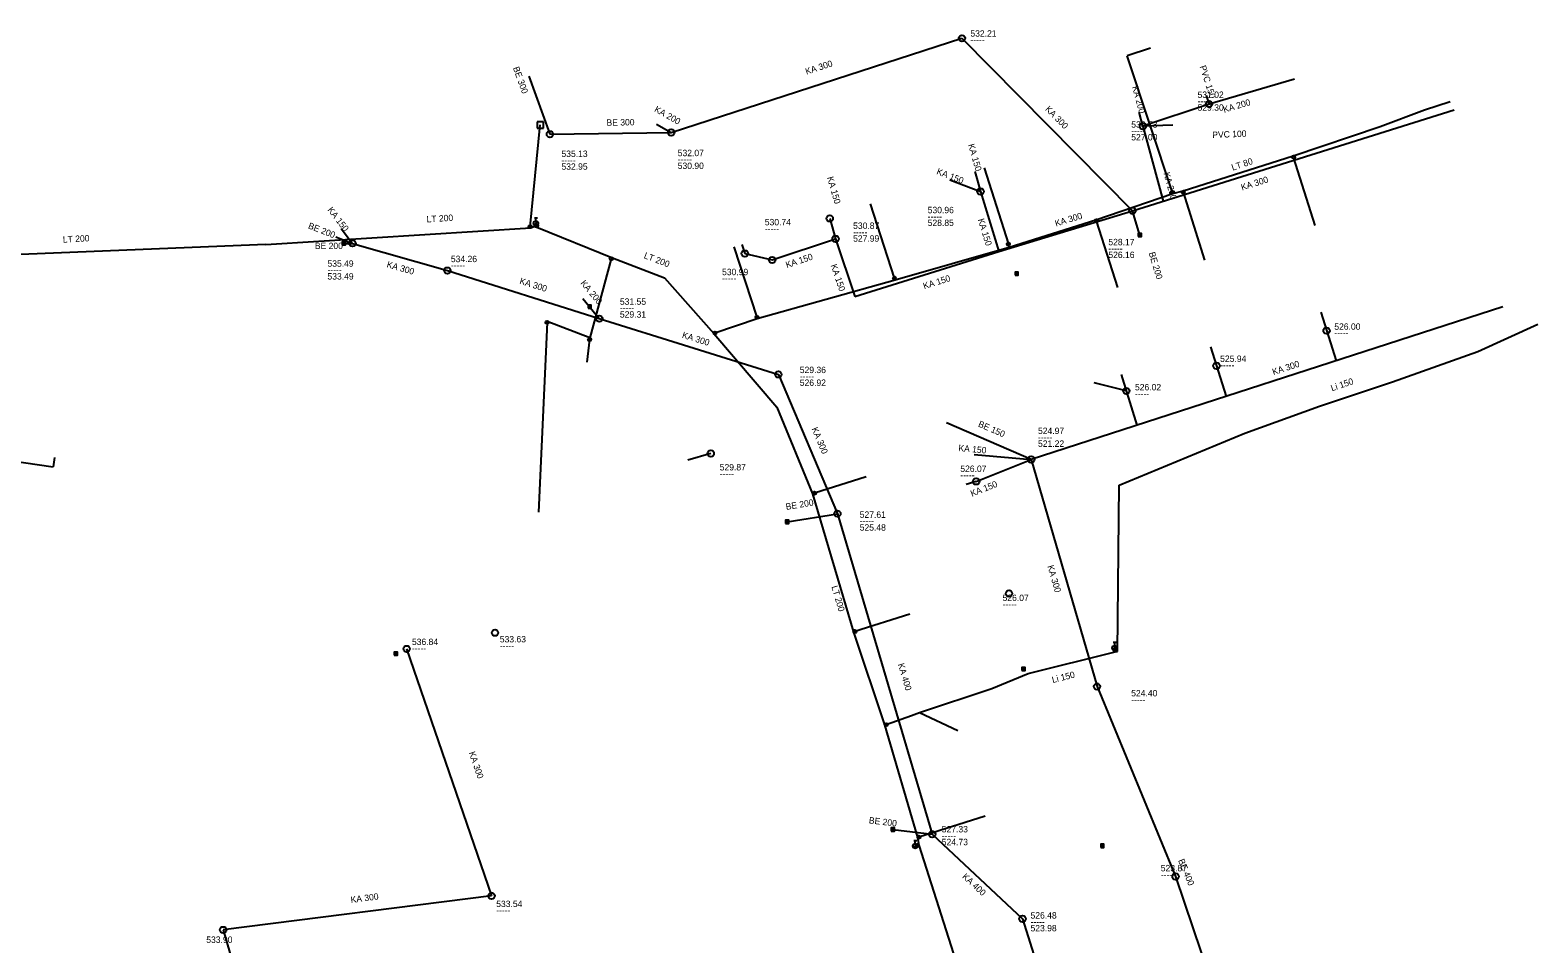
# Model space of a CAD drawing. Extents: x -769542 to -769122, y -1181691 to -1181360.
# Drawn here: x -769357.9 to -769122.2, y -1181503.2 to -1181360.4 of the extents above; entities that cross this region are included whole.
import ezdxf

# ---------------------------------------------------------------- set-up
doc = ezdxf.new("R2010")
doc.units = 0
for name, color, linetype in [('Level 19', 7, 'Continuous'), ('Level 20', 7, 'Continuous'), ('Level 21', 7, 'Continuous'), ('Level 24', 7, 'Continuous'), ('Level 26', 7, 'Continuous'), ('Level 29', 7, 'Continuous'), ('Level 40', 7, 'Continuous'), ('Level 41', 7, 'Continuous'), ('Level 44', 7, 'Continuous'), ('Level 45', 7, 'Continuous'), ('Level 46', 7, 'Continuous')]:
    doc.layers.add(name, color=color, linetype=linetype)

msp = doc.modelspace()

# ---------------------------------------------------------------- linework, layer by layer
at = {"layer": 'Level 19'}
for p, q in [((-769182.75, -1181363.17), (-769186.37, -1181364.36)), ((-769179.31, -1181385.73), (-769186.37, -1181364.36)), ((-769279.75, -1181391.1), (-769278.16, -1181375.19)), ((-769160.36, -1181380.2), (-769160.45, -1181380.04)), ((-769157, -1181390.91), (-769160.36, -1181380.2)), ((-769208.75, -1181381.9), (-769204.97, -1181393.84)), ((-769179.25, -1181385.92), (-769179.31, -1181385.73)), ((-769177.63, -1181385.47), (-769177.59, -1181385.7)), ((-769174.25, -1181396.33), (-769177.59, -1181385.7)), ((-769222.77, -1181399.16), (-769226.53, -1181387.52)), ((-769279.65, -1181391.3), (-769279.75, -1181391.1)), ((-769191.31, -1181390), (-769191.19, -1181390.17)), ((-769187.86, -1181400.63), (-769191.19, -1181390.17)), ((-769244.26, -1181405.26), (-769247.84, -1181394.26)), ((-769204.85, -1181394.31), (-769204.97, -1181393.84)), ((-769267.07, -1181396.11), (-769270.41, -1181408.5)), ((-769266.89, -1181395.96), (-769267.07, -1181396.11)), ((-769222.66, -1181399.42), (-769222.77, -1181399.16)), ((-769244.22, -1181405.43), (-769244.26, -1181405.26)), ((-769277.1, -1181406.06), (-769278.46, -1181435.74)), ((-769277.07, -1181405.94), (-769277.1, -1181406.06)), ((-769270.41, -1181408.5), (-769277.07, -1181405.94)), ((-769270.45, -1181408.75), (-769270.9, -1181412.3)), ((-769270.41, -1181408.5), (-769270.45, -1181408.75)), ((-769376.52, -1181425.51), (-769354.33, -1181428.62)), ((-769354.1, -1181427.21), (-769354.33, -1181428.62)), ((-769227.19, -1181430.21), (-769235.27, -1181432.76)), ((-769235.57, -1181432.87), (-769235.27, -1181432.76)), ((-769220.36, -1181451.66), (-769228.96, -1181454.4)), ((-769229.16, -1181454.48), (-769228.96, -1181454.4)), ((-769218.88, -1181467.07), (-769212.85, -1181469.89)), ((-769208.6, -1181483.28), (-769218.95, -1181486.55)), ((-769219.19, -1181486.6), (-769218.95, -1181486.55))]:
    msp.add_line(p, q, dxfattribs=at)
at = {"layer": 'Level 20'}
for p, q in [((-769139.91, -1181372.81), (-769135.9, -1181371.5)), ((-769146.83, -1181375.45), (-769139.91, -1181372.81)), ((-769160.45, -1181380.04), (-769146.83, -1181375.45)), ((-769177.63, -1181385.47), (-769160.45, -1181380.04)), ((-769191.31, -1181390), (-769179.25, -1181385.92)), ((-769179.25, -1181385.92), (-769177.63, -1181385.47)), ((-769279.65, -1181391.3), (-769278.99, -1181391.03)), ((-769278.99, -1181391.03), (-769278.71, -1181391.19)), ((-769278.73, -1181390.98), (-769278.84, -1181390.57)), ((-769278.71, -1181391.19), (-769278.73, -1181390.98)), ((-769204.85, -1181394.31), (-769191.31, -1181390)), ((-769321.1, -1181393.86), (-769279.65, -1181391.3)), ((-769278.71, -1181391.19), (-769266.89, -1181395.96)), ((-769321.1, -1181393.86), (-769371.45, -1181395.91)), ((-769222.66, -1181399.42), (-769204.85, -1181394.31)), ((-769266.89, -1181395.96), (-769258.74, -1181399.09)), ((-769258.74, -1181399.09), (-769251.02, -1181407.79)), ((-769244.22, -1181405.43), (-769222.66, -1181399.42)), ((-769250.85, -1181407.71), (-769244.22, -1181405.43)), ((-769131.58, -1181410.62), (-769122.17, -1181406.35)), ((-769251.02, -1181407.79), (-769250.85, -1181407.71)), ((-769251.02, -1181407.79), (-769241.16, -1181419.29)), ((-769144.92, -1181415.35), (-769131.58, -1181410.62)), ((-769156.29, -1181419.18), (-769144.92, -1181415.35)), ((-769241.16, -1181419.29), (-769235.57, -1181432.87)), ((-769168.01, -1181423.4), (-769156.29, -1181419.18)), ((-769187.65, -1181431.52), (-769168.01, -1181423.4)), ((-769235.57, -1181432.87), (-769229.16, -1181454.48)), ((-769187.88, -1181457.52), (-769187.65, -1181431.52)), ((-769229.16, -1181454.48), (-769224.35, -1181469)), ((-769188.33, -1181457.22), (-769188.34, -1181456.96)), ((-769201.88, -1181460.98), (-769188.27, -1181457.55)), ((-769188.27, -1181457.55), (-769188.33, -1181457.22)), ((-769188.27, -1181457.55), (-769187.88, -1181457.52)), ((-769207.54, -1181463.28), (-769201.88, -1181460.98)), ((-769218.88, -1181467.07), (-769207.54, -1181463.28)), ((-769224.35, -1181469), (-769224.06, -1181468.96)), ((-769224.06, -1181468.96), (-769220.09, -1181467.52)), ((-769220.09, -1181467.52), (-769218.88, -1181467.07)), ((-769224.35, -1181469), (-769219.19, -1181486.6)), ((-769219.19, -1181486.6), (-769218.94, -1181487.79)), ((-769218.94, -1181487.79), (-769219.19, -1181487.87)), ((-769218.94, -1181487.79), (-769212.39, -1181508.39)), ((-769219.19, -1181487.87), (-769219.52, -1181487.95))]:
    msp.add_line(p, q, dxfattribs=at)
at = {"layer": 'Level 21'}
for p, q in [((-769279.134, -1181390.801), (-769278.544, -1181390.338)), ((-769279.09, -1181389.695), (-769278.59, -1181389.695)), ((-769278.84, -1181390.195), (-769278.84, -1181389.695)), ((-769188.634, -1181457.191), (-769188.044, -1181456.728)), ((-769188.59, -1181456.085), (-769188.09, -1181456.085)), ((-769188.34, -1181456.585), (-769188.34, -1181456.085)), ((-769219.814, -1181488.181), (-769219.224, -1181487.718)), ((-769219.77, -1181487.075), (-769219.27, -1181487.075)), ((-769219.52, -1181487.575), (-769219.52, -1181487.075))]:
    msp.add_line(p, q, dxfattribs=at)
for centre in [(-769278.84, -1181390.57), (-769188.34, -1181456.96), (-769219.52, -1181487.95)]:
    msp.add_circle(centre, 0.375, dxfattribs=at)
at = {"layer": 'Level 26'}
for centre in [(-769160.36, -1181380.2), (-769179.31, -1181385.73), (-769177.59, -1181385.7), (-769279.75, -1181391.1), (-769278.73, -1181390.98), (-769191.19, -1181390.17), (-769267.07, -1181396.11), (-769204.97, -1181393.84), (-769222.77, -1181399.16), (-769244.26, -1181405.26), (-769277.1, -1181406.06), (-769250.85, -1181407.71), (-769270.45, -1181408.75), (-769235.27, -1181432.76), (-769228.96, -1181454.4), (-769188.33, -1181457.22), (-769224.06, -1181468.96), (-769219.19, -1181487.87), (-769218.95, -1181486.55)]:
    msp.add_circle(centre, 0.25, dxfattribs=at)
at = {"layer": 'Level 29'}
for p, q in [((-769277.66, -1181374.69), (-769278.66, -1181374.69)), ((-769278.66, -1181374.69), (-769278.66, -1181375.69)), ((-769278.66, -1181375.69), (-769277.66, -1181375.69)), ((-769277.66, -1181375.69), (-769277.66, -1181374.69))]:
    msp.add_line(p, q, dxfattribs=at)
at = {"layer": 'Level 40'}
for p, q in [((-769257.69, -1181376.37), (-769212.22, -1181361.64)), ((-769212.22, -1181361.64), (-769185.56, -1181388.6)), ((-769279.93, -1181367.57), (-769276.65, -1181376.64)), ((-769160.22, -1181368.02), (-769173.59, -1181371.92)), ((-769173.59, -1181371.92), (-769183.93, -1181375.38)), ((-769185.56, -1181388.6), (-769135.28, -1181372.8)), ((-769276.65, -1181376.64), (-769257.69, -1181376.37)), ((-769183.93, -1181375.38), (-769180.75, -1181387.09)), ((-769209.32, -1181385.6), (-769206.44, -1181395)), ((-769206.44, -1181395), (-769185.56, -1181388.6)), ((-769232.9, -1181389.81), (-769231.99, -1181393)), ((-769241.9, -1181396.3), (-769231.99, -1181393)), ((-769231.99, -1181393), (-769228.95, -1181402.03)), ((-769307.52, -1181393.7), (-769292.69, -1181397.96)), ((-769246.17, -1181395.3), (-769241.9, -1181396.3)), ((-769228.95, -1181402.03), (-769206.44, -1181395)), ((-769292.69, -1181397.96), (-769268.94, -1181405.47)), ((-769127.67, -1181403.61), (-769201.4, -1181427.5)), ((-769268.94, -1181405.47), (-769240.93, -1181414.2)), ((-769240.93, -1181414.2), (-769231.7, -1181435.97)), ((-769210, -1181430.93), (-769201.4, -1181427.5)), ((-769201.4, -1181427.5), (-769191.1, -1181463.01)), ((-769231.7, -1181435.97), (-769216.88, -1181486.1)), ((-769299.06, -1181457.11), (-769285.78, -1181495.74)), ((-769191.1, -1181463.01), (-769178.82, -1181492.7)), ((-769216.88, -1181486.1), (-769202.76, -1181499.32)), ((-769178.82, -1181492.7), (-769159.28, -1181550.75)), ((-769285.78, -1181495.74), (-769327.75, -1181501.05)), ((-769202.76, -1181499.32), (-769190.37, -1181538.88)), ((-769327.75, -1181501.05), (-769324.09, -1181513.66))]:
    msp.add_line(p, q, dxfattribs=at)
at = {"layer": 'Level 41'}
for centre in [(-769212.22, -1181361.64), (-769173.59, -1181371.92), (-769276.65, -1181376.64), (-769257.69, -1181376.37), (-769183.93, -1181375.38), (-769209.32, -1181385.6), (-769185.56, -1181388.6), (-769232.9, -1181389.81), (-769307.52, -1181393.7), (-769231.99, -1181393), (-769246.17, -1181395.3), (-769241.9, -1181396.3), (-769292.69, -1181397.96), (-769268.94, -1181405.47), (-769155.21, -1181407.36), (-769172.42, -1181412.85), (-769240.93, -1181414.2), (-769240.93, -1181414.2), (-769186.52, -1181416.78), (-769251.5, -1181426.56), (-769201.4, -1181427.5), (-769210, -1181430.93), (-769231.7, -1181435.97), (-769204.86, -1181448.45), (-769285.24, -1181454.59), (-769299.06, -1181457.11), (-769191.1, -1181463.01), (-769216.88, -1181486.1), (-769178.82, -1181492.7), (-769285.78, -1181495.74), (-769202.76, -1181499.32), (-769327.75, -1181501.05)]:
    msp.add_circle(centre, 0.5, dxfattribs=at)
at = {"layer": 'Level 45'}
for p, q in [((-769174.02, -1181370.57), (-769173.59, -1181371.92)), ((-769183.93, -1181375.38), (-769184.52, -1181373.2)), ((-769259.99, -1181375.07), (-769257.69, -1181376.37)), ((-769179.26, -1181375.2), (-769183.93, -1181375.38)), ((-769214.1, -1181383.77), (-769209.32, -1181385.6)), ((-769210.22, -1181382.48), (-769209.32, -1181385.6)), ((-769184.42, -1181392.4), (-769185.56, -1181388.6)), ((-769310.11, -1181392.69), (-769307.52, -1181393.7)), ((-769309.32, -1181391.38), (-769307.52, -1181393.7)), ((-769308.89, -1181393.7), (-769307.52, -1181393.7)), ((-769246.62, -1181393.87), (-769246.17, -1181395.3)), ((-769271.52, -1181402.34), (-769268.94, -1181405.47)), ((-769156.12, -1181404.47), (-769153.73, -1181412.06)), ((-769173.35, -1181409.87), (-769170.93, -1181417.63)), ((-769187.32, -1181414.2), (-769184.86, -1181422.14)), ((-769186.52, -1181416.78), (-769191.55, -1181415.51)), ((-769201.4, -1181427.5), (-769214.62, -1181421.75)), ((-769251.5, -1181426.56), (-769255.09, -1181427.6)), ((-769210.32, -1181426.71), (-769201.4, -1181427.5)), ((-769210, -1181430.93), (-769211.59, -1181431.41)), ((-769239.55, -1181437.26), (-769231.7, -1181435.97)), ((-769223.02, -1181485.36), (-769216.88, -1181486.1))]:
    msp.add_line(p, q, dxfattribs=at)
at = {"layer": 'Level 46'}
for p, q in [((-769184.67, -1181392.4), (-769184.17, -1181392.4)), ((-769309.14, -1181393.7), (-769308.64, -1181393.7)), ((-769203.92, -1181398.44), (-769203.42, -1181398.44)), ((-769270.68, -1181403.61), (-769270.18, -1181403.61)), ((-769239.8, -1181437.26), (-769239.3, -1181437.26)), ((-769301.01, -1181457.86), (-769300.51, -1181457.86)), ((-769202.86, -1181460.26), (-769202.36, -1181460.26)), ((-769223.27, -1181485.36), (-769222.77, -1181485.36)), ((-769190.52, -1181487.91), (-769190.02, -1181487.91))]:
    msp.add_line(p, q, dxfattribs=at)
for points in [[(-769309.14, -1181393.951), (-769308.6395, -1181393.951), (-769308.6395, -1181393.4495), (-769309.14, -1181393.4495)], [(-769184.67, -1181392.651), (-769184.1695, -1181392.651), (-769184.1695, -1181392.1495), (-769184.67, -1181392.1495)], [(-769203.92, -1181398.691), (-769203.4195, -1181398.691), (-769203.4195, -1181398.1895), (-769203.92, -1181398.1895)], [(-769270.68, -1181403.861), (-769270.1795, -1181403.861), (-769270.1795, -1181403.3595), (-769270.68, -1181403.3595)], [(-769239.8, -1181437.511), (-769239.2995, -1181437.511), (-769239.2995, -1181437.0095), (-769239.8, -1181437.0095)], [(-769301.01, -1181458.111), (-769300.5095, -1181458.111), (-769300.5095, -1181457.6095), (-769301.01, -1181457.6095)], [(-769202.86, -1181460.511), (-769202.3595, -1181460.511), (-769202.3595, -1181460.0095), (-769202.86, -1181460.0095)], [(-769223.27, -1181485.611), (-769222.7695, -1181485.611), (-769222.7695, -1181485.1095), (-769223.27, -1181485.1095)], [(-769190.52, -1181488.161), (-769190.0195, -1181488.161), (-769190.0195, -1181487.6595), (-769190.52, -1181487.6595)]]:
    msp.add_lwpolyline(points, close=True, dxfattribs=at)

# ---------------------------------------------------------------- texts
at = {"layer": 'Level 24'}
for s, rotation, p in [('LT 80', 18.624, (-769169.88, -1181382.35)), ('LT 200', 3.534, (-769295.91, -1181390.43)), ('LT 200', 3.1, (-769352.79, -1181393.6)), ('LT 200', 338.991, (-769262.05, -1181395.99)), ('Li 150', 18.616, (-769154.36, -1181416.84)), ('LT 200', 286.522, (-769232.65, -1181447.38)), ('Li 150', 14.145, (-769198.02, -1181462.46))]:
    msp.add_text(s, height=1, rotation=rotation, dxfattribs=at).set_placement(p)
at = {"layer": 'Level 44'}
for s, p in [('532.21', (-769210.9, -1181361.38)), ('-----', (-769210.9, -1181362.38)), ('531.02', (-769175.38, -1181370.96)), ('529.30', (-769175.38, -1181372.96)), ('-----', (-769175.38, -1181371.96)), ('530.73', (-769185.75, -1181375.61)), ('527.00', (-769185.75, -1181377.61)), ('-----', (-769185.75, -1181376.61)), ('535.13', (-769274.85, -1181380.19)), ('532.07', (-769256.67, -1181380.07)), ('532.95', (-769274.85, -1181382.19)), ('-----', (-769274.85, -1181381.19)), ('530.90', (-769256.67, -1181382.07)), ('-----', (-769256.67, -1181381.07)), ('530.96', (-769217.58, -1181388.99)), ('530.74', (-769243.05, -1181390.88)), ('530.87', (-769229.24, -1181391.44)), ('528.85', (-769217.58, -1181390.99)), ('-----', (-769217.58, -1181389.99)), ('-----', (-769243.05, -1181391.88)), ('527.99', (-769229.24, -1181393.44)), ('-----', (-769229.24, -1181392.44)), ('528.17', (-769189.33, -1181394)), ('BE 200', (-769313.41, -1181394.59)), ('534.26', (-769292.14, -1181396.64)), ('526.16', (-769189.33, -1181396)), ('-----', (-769189.33, -1181395)), ('535.49', (-769311.44, -1181397.36)), ('-----', (-769311.44, -1181398.36)), ('-----', (-769292.14, -1181397.64)), ('530.99', (-769249.73, -1181398.68)), ('533.49', (-769311.44, -1181399.36)), ('-----', (-769249.73, -1181399.68)), ('531.55', (-769265.71, -1181403.31)), ('529.31', (-769265.71, -1181405.31)), ('-----', (-769265.71, -1181404.31)), ('526.00', (-769154, -1181407.22)), ('-----', (-769154, -1181408.22)), ('525.94', (-769171.85, -1181412.24)), ('529.36', (-769237.58, -1181413.99)), ('-----', (-769237.58, -1181414.99)), ('-----', (-769171.85, -1181413.24)), ('526.92', (-769237.58, -1181415.99)), ('526.02', (-769185.17, -1181416.69)), ('-----', (-769185.17, -1181417.69)), ('524.97', (-769200.33, -1181423.52)), ('-----', (-769200.33, -1181424.52)), ('521.22', (-769200.33, -1181425.52)), ('529.87', (-769250.1, -1181429.21)), ('526.07', (-769212.48, -1181429.44)), ('-----', (-769250.1, -1181430.21)), ('-----', (-769212.48, -1181430.44)), ('527.61', (-769228.21, -1181436.62)), ('525.48', (-769228.21, -1181438.62)), ('-----', (-769228.21, -1181437.62)), ('526.07', (-769205.87, -1181449.62)), ('-----', (-769205.87, -1181450.62)), ('536.84', (-769298.23, -1181456.51)), ('-----', (-769298.23, -1181457.51)), ('533.63', (-769284.49, -1181456.1)), ('-----', (-769284.49, -1181457.1)), ('524.40', (-769185.76, -1181464.54)), ('-----', (-769185.76, -1181465.54)), ('527.33', (-769215.38, -1181485.81)), ('524.73', (-769215.38, -1181487.81)), ('-----', (-769215.38, -1181486.81)), ('523.87', (-769181.13, -1181491.89)), ('-----', (-769181.13, -1181492.89)), ('533.54', (-769285.05, -1181497.48)), ('-----', (-769285.05, -1181498.48)), ('526.48', (-769201.5, -1181499.28)), ('523.98', (-769201.5, -1181501.28)), ('-----', (-769201.5, -1181500.28)), ('533.90', (-769330.39, -1181503.08))]:
    msp.add_text(s, height=1, dxfattribs=at).set_placement(p)
for s, rotation, p in [('KA 300', 17.95, (-769236.53, -1181367.33)), ('BE 300', 289.89, (-769282.45, -1181366.27)), ('PVC 150', 287.668, (-769175.07, -1181366.05)), ('KA 200', 285.144, (-769185.63, -1181369.24)), ('KA 200', 330.583, (-769260.42, -1181373.03)), ('KA 300', 314.679, (-769199.29, -1181372.8)), ('KA 200', 16.262, (-769171.22, -1181373.29)), ('BE 300', 0.816, (-769267.8, -1181375.31)), ('PVC 100', 2.293, (-769173.06, -1181377.24)), ('KA 150', 286.042, (-769211.28, -1181378.29)), ('KA 150', 285.922, (-769233.33, -1181383.41)), ('KA 150', 339.076, (-769216.29, -1181382.85)), ('KA 200', 285.193, (-769180.71, -1181382.73)), ('KA 300', 17.445, (-769168.41, -1181385.45)), ('KA 150', 307.764, (-769311.49, -1181388.49)), ('BE 200', 338.678, (-769314.55, -1181391.33)), ('KA 150', 287.034, (-769209.75, -1181389.99)), ('KA 300', 17.041, (-769197.51, -1181391.09)), ('KA 150', 18.418, (-769239.6, -1181397.58)), ('BE 200', 286.699, (-769183.03, -1181395.21)), ('KA 300', 343.973, (-769302.25, -1181397.42)), ('KA 150', 288.6, (-769232.77, -1181397.14)), ('KA 300', 342.452, (-769281.48, -1181399.99)), ('KA 200', 309.446, (-769271.94, -1181399.96)), ('KA 150', 17.351, (-769218.12, -1181400.88)), ('KA 300', 342.689, (-769256.07, -1181408.44)), ('KA 300', 17.953, (-769163.51, -1181414.31)), ('BE 150', 336.494, (-769209.78, -1181422.31)), ('KA 300', 292.976, (-769235.76, -1181422.7)), ('KA 150', 354.934, (-769212.81, -1181426.18)), ('KA 150', 21.744, (-769210.65, -1181433.34)), ('BE 200', 9.332, (-769239.69, -1181435.39)), ('KA 300', 286.175, (-769198.87, -1181444.18)), ('KA 400', 286.469, (-769222.26, -1181459.52)), ('KA 300', 288.972, (-769289.35, -1181473.35)), ('BE 200', 353.128, (-769226.82, -1181484.38)), ('BE 400', 292.47, (-769178.44, -1181490.19)), ('KA 400', 316.885, (-769212.25, -1181492.82)), ('KA 300', 7.211, (-769307.75, -1181496.84))]:
    msp.add_text(s, height=1, rotation=rotation, dxfattribs=at).set_placement(p)

doc.saveas('drawing.dxf')
